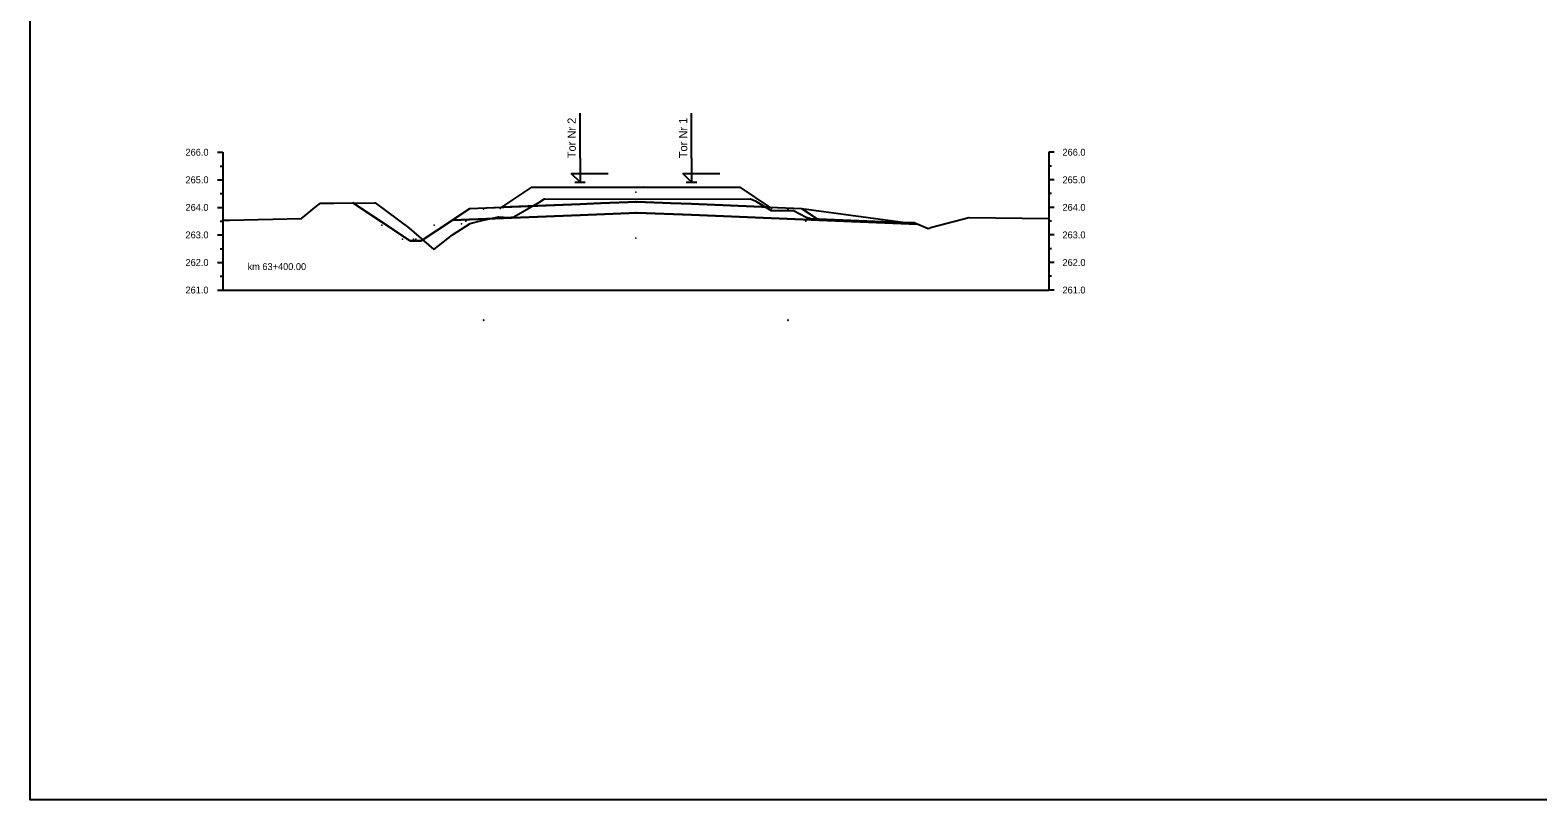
# Model space of a CAD drawing. Extents: x -1 to 65640748, y -22 to 5530284.
# Drawn here: x 2476.3 to 2531.1, y 966.4 to 994.4 of the extents above; entities that cross this region are included whole.
import ezdxf

# ---------------------------------------------------------------- set-up
doc = ezdxf.new("R2010")
doc.units = 0
for name, color, linetype in [('IR_cross_section', 7, 'Continuous'), ('IR_cross_section_tytul', 7, 'Continuous'), ('IR_default', 7, 'Continuous'), ('TOR_PRZEK_P-komponent', 7, 'Continuous'), ('TOR_PRZEK_P-obwiednia robo ziemnych', 7, 'Continuous'), ('TOR_PRZEK_P-odwodnienie', 7, 'Continuous'), ('TOR_PRZEK_P-teren istniejacy', 7, 'Continuous'), ('TOR_PRZEK_P-tluczen+miedzytorze', 7, 'Continuous'), ('TOR_PRZEK_P-tory projektowane', 7, 'Continuous'), ('TOR_PRZEK_P-uklad odniesienia', 7, 'Continuous'), ('TOR_PRZEK_P-warstwa ochronna I', 7, 'Continuous'), ('TOR_PRZEK_P-warstwa ochronna II', 7, 'Continuous')]:
    doc.layers.add(name, color=color, linetype=linetype)

msp = doc.modelspace()

# ---------------------------------------------------------------- linework, layer by layer
for points in [[(2489.55, 987.108), (2488.051, 988.107)], [(2504.352, 987.901), (2504.991, 987.476), (2508.566, 987.333)], [(2490.535, 986.718), (2490.135, 986.718), (2489.55, 987.108)]]:
    msp.add_lwpolyline(points)
at = {"layer": 'IR_cross_section'}
msp.add_lwpolyline([(2476.328, 994.938), (2676.328, 994.938), (2676.328, 966.438), (2476.328, 966.438)], close=True, dxfattribs=at)
at = {"layer": 'IR_default'}
for points in [[(2488.051, 988.107), (2488.857, 987.57), (2489.55, 987.108), (2489.816, 986.93), (2490.135, 986.718), (2490.535, 986.718), (2491.664, 987.471), (2492.303, 987.897), (2493.462, 987.943), (2494.553, 988.67), (2498.052, 988.67), (2498.14, 988.67), (2498.603, 988.67), (2500.126, 988.67), (2502.103, 988.67), (2503.186, 987.948), (2504.352, 987.901), (2504.991, 987.476), (2508.566, 987.333)], [(2486.877, 988.093), (2486.877, 988.094), (2486.877, 988.093), (2486.877, 988.093), (2486.877, 988.093), (2486.878, 988.093), (2486.877, 988.093), (2486.878, 988.094)], [(2488.863, 988.102), (2488.863, 988.103), (2488.863, 988.102), (2488.863, 988.102), (2488.863, 988.102), (2488.864, 988.102), (2488.863, 988.102), (2488.864, 988.103)], [(2495.015, 988.249), (2495.015, 988.25), (2495.015, 988.249), (2495.015, 988.249), (2495.015, 988.249), (2495.016, 988.249), (2495.015, 988.249), (2495.016, 988.25)], [(2502.499, 988.249), (2502.498, 988.25), (2502.499, 988.249), (2502.498, 988.249), (2502.499, 988.249), (2502.499, 988.249), (2502.499, 988.249), (2502.499, 988.25)], [(2486.188, 987.537), (2486.188, 987.537), (2486.188, 987.537), (2486.188, 987.536), (2486.188, 987.537), (2486.189, 987.536), (2486.188, 987.537), (2486.189, 987.537)], [(2492.303, 987.897), (2491.664, 987.471), (2490.535, 986.718)], [(2492.303, 987.897), (2492.302, 987.897), (2492.303, 987.897), (2492.302, 987.896), (2492.303, 987.897), (2492.303, 987.896), (2492.303, 987.897), (2492.303, 987.897)], [(2493.345, 987.598), (2493.345, 987.599), (2493.345, 987.598), (2493.345, 987.598), (2493.345, 987.598), (2493.346, 987.598), (2493.345, 987.598), (2493.346, 987.599)], [(2493.894, 987.59), (2493.893, 987.59), (2493.894, 987.59), (2493.893, 987.589), (2493.894, 987.59), (2493.894, 987.589), (2493.894, 987.59), (2493.894, 987.59)], [(2503.25, 987.83), (2503.249, 987.831), (2503.25, 987.83), (2503.249, 987.83), (2503.25, 987.83), (2503.25, 987.83), (2503.25, 987.83), (2503.25, 987.831)], [(2504.062, 987.824), (2504.062, 987.825), (2504.062, 987.824), (2504.062, 987.824), (2504.062, 987.824), (2504.063, 987.824), (2504.062, 987.824), (2504.063, 987.825)], [(2504.353, 987.901), (2504.352, 987.902), (2504.353, 987.901), (2504.352, 987.901), (2504.353, 987.901), (2504.353, 987.901), (2504.353, 987.901), (2504.353, 987.902)], [(2504.67, 987.536), (2504.67, 987.536), (2504.67, 987.536), (2504.67, 987.535), (2504.67, 987.536), (2504.671, 987.535), (2504.67, 987.536), (2504.671, 987.536)], [(2510.429, 987.565), (2510.428, 987.565), (2510.429, 987.565), (2510.428, 987.564), (2510.429, 987.565), (2510.429, 987.564), (2510.429, 987.565), (2510.429, 987.565)], [(2492.31, 987.351), (2492.31, 987.352), (2492.31, 987.351), (2492.31, 987.351), (2492.31, 987.351), (2492.311, 987.351), (2492.31, 987.351), (2492.311, 987.352)], [(2508.439, 987.386), (2508.439, 987.387), (2508.439, 987.386), (2508.439, 987.386), (2508.439, 987.386), (2508.44, 987.386), (2508.439, 987.386), (2508.44, 987.387)], [(2508.947, 987.171), (2508.946, 987.171), (2508.947, 987.171), (2508.946, 987.17), (2508.947, 987.171), (2508.947, 987.17), (2508.947, 987.171), (2508.947, 987.171)], [(2490.988, 986.413), (2490.987, 986.414), (2490.988, 986.413), (2490.987, 986.413), (2490.988, 986.413), (2490.988, 986.413), (2490.988, 986.413), (2490.988, 986.414)]]:
    msp.add_lwpolyline(points, dxfattribs=at)
at = {"layer": 'TOR_PRZEK_P-komponent'}
msp.add_lwpolyline([(2494.553, 988.67), (2498.052, 988.67), (2498.603, 988.67), (2502.103, 988.67), (2503.186, 987.948), (2500.352, 988.061), (2499.602, 988.091), (2498.383, 988.14), (2497.053, 988.087), (2496.303, 988.057), (2493.462, 987.943), (2493.462, 987.943)], close=True, dxfattribs=at)
for points in [[(2498.054, 988.67), (2498.053, 988.67), (2498.054, 988.67), (2498.053, 988.669), (2498.054, 988.67), (2498.054, 988.669), (2498.054, 988.67), (2498.054, 988.67)], [(2498.602, 988.67), (2498.601, 988.67), (2498.602, 988.67), (2498.601, 988.669), (2498.602, 988.67), (2498.602, 988.669), (2498.602, 988.67), (2498.602, 988.67)], [(2498.327, 988.487), (2498.326, 988.488), (2498.327, 988.487), (2498.326, 988.487), (2498.327, 988.487), (2498.327, 988.487), (2498.327, 988.487), (2498.327, 988.488)], [(2498.329, 988.487), (2498.328, 988.488), (2498.329, 988.487), (2498.328, 988.487), (2498.329, 988.487), (2498.329, 988.487), (2498.329, 988.487), (2498.329, 988.488)]]:
    msp.add_lwpolyline(points, dxfattribs=at)
at = {"layer": 'TOR_PRZEK_P-obwiednia robo ziemnych'}
for points in [[(2487.892, 988.093), (2487.892, 988.094), (2487.892, 988.093), (2487.892, 988.093), (2487.892, 988.093), (2487.893, 988.093), (2487.892, 988.093), (2487.893, 988.094)], [(2487.892, 988.093), (2487.892, 988.094), (2487.892, 988.093), (2487.892, 988.093), (2487.892, 988.093), (2487.893, 988.093), (2487.892, 988.093), (2487.893, 988.094)], [(2488.051, 988.107), (2488.051, 988.107), (2488.051, 988.107), (2488.051, 988.106), (2488.051, 988.107), (2488.052, 988.106), (2488.051, 988.107), (2488.052, 988.107)], [(2488.051, 988.107), (2488.051, 988.107), (2488.051, 988.107), (2488.051, 988.106), (2488.051, 988.107), (2488.052, 988.106), (2488.051, 988.107), (2488.052, 988.107)], [(2489.1, 987.288), (2489.1, 987.288), (2489.1, 987.288), (2489.1, 987.287), (2489.1, 987.288), (2489.101, 987.287), (2489.1, 987.288), (2489.101, 987.288)], [(2489.1, 987.288), (2489.1, 987.288), (2489.1, 987.288), (2489.1, 987.287), (2489.1, 987.288), (2489.101, 987.287), (2489.1, 987.288), (2489.101, 987.288)], [(2491, 987.288), (2490.999, 987.288), (2491, 987.288), (2490.999, 987.287), (2491, 987.288), (2491, 987.287), (2491, 987.288), (2491, 987.288)], [(2491, 987.288), (2490.999, 987.288), (2491, 987.288), (2490.999, 987.287), (2491, 987.288), (2491, 987.287), (2491, 987.288), (2491, 987.288)], [(2492, 987.338), (2491.999, 987.338), (2492, 987.338), (2491.999, 987.337), (2492, 987.338), (2492, 987.337), (2492, 987.338), (2492, 987.338)], [(2492, 987.338), (2491.999, 987.338), (2492, 987.338), (2491.999, 987.337), (2492, 987.338), (2492, 987.337), (2492, 987.338), (2492, 987.338)], [(2492.149, 987.437), (2492.149, 987.438), (2492.149, 987.437), (2492.149, 987.437), (2492.149, 987.437), (2492.15, 987.437), (2492.149, 987.437), (2492.15, 987.438)], [(2492.149, 987.437), (2492.149, 987.438), (2492.149, 987.437), (2492.149, 987.437), (2492.149, 987.437), (2492.15, 987.437), (2492.149, 987.437), (2492.15, 987.438)], [(2489.85, 986.788), (2489.849, 986.788), (2489.85, 986.788), (2489.849, 986.787), (2489.85, 986.788), (2489.85, 986.787), (2489.85, 986.788), (2489.85, 986.788)], [(2489.85, 986.788), (2489.849, 986.788), (2489.85, 986.788), (2489.849, 986.787), (2489.85, 986.788), (2489.85, 986.787), (2489.85, 986.788), (2489.85, 986.788)], [(2490.135, 986.718), (2490.134, 986.718), (2490.135, 986.718), (2490.134, 986.717), (2490.135, 986.718), (2490.135, 986.717), (2490.135, 986.718), (2490.135, 986.718)], [(2490.135, 986.718), (2490.134, 986.718), (2490.135, 986.718), (2490.134, 986.717), (2490.135, 986.718), (2490.135, 986.717), (2490.135, 986.718), (2490.135, 986.718)], [(2490.25, 986.788), (2490.249, 986.788), (2490.25, 986.788), (2490.249, 986.787), (2490.25, 986.788), (2490.25, 986.787), (2490.25, 986.788), (2490.25, 986.788)], [(2490.25, 986.788), (2490.249, 986.788), (2490.25, 986.788), (2490.249, 986.787), (2490.25, 986.788), (2490.25, 986.787), (2490.25, 986.788), (2490.25, 986.788)], [(2490.535, 986.718), (2490.534, 986.718), (2490.535, 986.718), (2490.534, 986.717), (2490.535, 986.718), (2490.535, 986.717), (2490.535, 986.718), (2490.535, 986.718)], [(2490.535, 986.718), (2490.534, 986.718), (2490.535, 986.718), (2490.534, 986.717), (2490.535, 986.718), (2490.535, 986.717), (2490.535, 986.718), (2490.535, 986.718)]]:
    msp.add_lwpolyline(points, dxfattribs=at)
at = {"layer": 'TOR_PRZEK_P-odwodnienie'}
msp.add_lwpolyline([(2490.334, 986.788), (2490.334, 986.788), (2490.334, 986.788), (2490.334, 986.787), (2490.334, 986.788), (2490.335, 986.787), (2490.334, 986.788), (2490.335, 986.788)], dxfattribs=at)
at = {"layer": 'TOR_PRZEK_P-teren istniejacy'}
msp.add_lwpolyline([(2483.328, 987.473), (2483.57, 987.476), (2486.188, 987.537), (2486.732, 987.984), (2486.877, 988.093), (2487.354, 988.088), (2488.863, 988.102), (2490.084, 987.192), (2490.988, 986.413), (2491.674, 986.947), (2492.31, 987.351), (2492.688, 987.453), (2493.345, 987.598), (2493.709, 987.565), (2493.894, 987.59), (2494.84, 988.135), (2495.015, 988.249), (2500.961, 988.241), (2502.499, 988.249), (2502.667, 988.169), (2503.25, 987.83), (2503.931, 987.83), (2504.062, 987.824), (2504.514, 987.586), (2504.67, 987.536), (2508.188, 987.39), (2508.439, 987.386), (2508.947, 987.171), (2509.079, 987.221), (2510.429, 987.565), (2513.328, 987.528)], dxfattribs=at)
at = {"layer": 'TOR_PRZEK_P-tluczen+miedzytorze'}
for points in [[(2494.553, 988.67), (2494.552, 988.67), (2494.553, 988.67), (2494.552, 988.669), (2494.553, 988.67), (2494.553, 988.669), (2494.553, 988.67), (2494.553, 988.67)], [(2494.553, 988.67), (2494.552, 988.67), (2494.553, 988.67), (2494.552, 988.669), (2494.553, 988.67), (2494.553, 988.669), (2494.553, 988.67), (2494.553, 988.67)], [(2496.303, 988.67), (2496.302, 988.67), (2496.303, 988.67), (2496.302, 988.669), (2496.303, 988.67), (2496.303, 988.669), (2496.303, 988.67), (2496.303, 988.67)], [(2497.059, 988.67), (2497.058, 988.67), (2497.059, 988.67), (2497.058, 988.669), (2497.059, 988.67), (2497.059, 988.669), (2497.059, 988.67), (2497.059, 988.67)], [(2498.053, 988.67), (2498.052, 988.67), (2498.053, 988.67), (2498.052, 988.669), (2498.053, 988.67), (2498.053, 988.669), (2498.053, 988.67), (2498.053, 988.67)], [(2498.053, 988.67), (2498.052, 988.67), (2498.053, 988.67), (2498.052, 988.669), (2498.053, 988.67), (2498.053, 988.669), (2498.053, 988.67), (2498.053, 988.67)], [(2498.603, 988.67), (2498.602, 988.67), (2498.603, 988.67), (2498.602, 988.669), (2498.603, 988.67), (2498.603, 988.669), (2498.603, 988.67), (2498.603, 988.67)], [(2498.603, 988.67), (2498.602, 988.67), (2498.603, 988.67), (2498.602, 988.669), (2498.603, 988.67), (2498.603, 988.669), (2498.603, 988.67), (2498.603, 988.67)], [(2499.597, 988.67), (2499.596, 988.67), (2499.597, 988.67), (2499.596, 988.669), (2499.597, 988.67), (2499.597, 988.669), (2499.597, 988.67), (2499.597, 988.67)], [(2500.353, 988.67), (2500.352, 988.67), (2500.353, 988.67), (2500.352, 988.669), (2500.353, 988.67), (2500.353, 988.669), (2500.353, 988.67), (2500.353, 988.67)], [(2502.103, 988.67), (2502.102, 988.67), (2502.103, 988.67), (2502.102, 988.669), (2502.103, 988.67), (2502.103, 988.669), (2502.103, 988.67), (2502.103, 988.67)], [(2502.103, 988.67), (2502.102, 988.67), (2502.103, 988.67), (2502.102, 988.669), (2502.103, 988.67), (2502.103, 988.669), (2502.103, 988.67), (2502.103, 988.67)], [(2497.059, 988.083), (2497.058, 988.083), (2497.059, 988.083), (2497.058, 988.082), (2497.059, 988.083), (2497.059, 988.082), (2497.059, 988.083), (2497.059, 988.083)], [(2498.327, 988.487), (2498.326, 988.488), (2498.327, 988.487), (2498.326, 988.487), (2498.327, 988.487), (2498.327, 988.487), (2498.327, 988.487), (2498.327, 988.488)], [(2498.327, 988.487), (2498.326, 988.488), (2498.327, 988.487), (2498.326, 988.487), (2498.327, 988.487), (2498.327, 988.487), (2498.327, 988.487), (2498.327, 988.488)], [(2498.327, 988.146), (2498.326, 988.147), (2498.327, 988.146), (2498.326, 988.146), (2498.327, 988.146), (2498.327, 988.146), (2498.327, 988.146), (2498.327, 988.147)], [(2498.327, 988.146), (2498.326, 988.147), (2498.327, 988.146), (2498.326, 988.146), (2498.327, 988.146), (2498.327, 988.146), (2498.327, 988.146), (2498.327, 988.147)], [(2498.329, 988.487), (2498.328, 988.488), (2498.329, 988.487), (2498.328, 988.487), (2498.329, 988.487), (2498.329, 988.487), (2498.329, 988.487), (2498.329, 988.488)], [(2498.329, 988.487), (2498.328, 988.488), (2498.329, 988.487), (2498.328, 988.487), (2498.329, 988.487), (2498.329, 988.487), (2498.329, 988.487), (2498.329, 988.488)], [(2498.329, 988.146), (2498.328, 988.147), (2498.329, 988.146), (2498.328, 988.146), (2498.329, 988.146), (2498.329, 988.146), (2498.329, 988.146), (2498.329, 988.147)], [(2498.329, 988.146), (2498.328, 988.147), (2498.329, 988.146), (2498.328, 988.146), (2498.329, 988.146), (2498.329, 988.146), (2498.329, 988.146), (2498.329, 988.147)], [(2499.597, 988.083), (2499.596, 988.083), (2499.597, 988.083), (2499.596, 988.082), (2499.597, 988.083), (2499.597, 988.082), (2499.597, 988.083), (2499.597, 988.083)], [(2493.398, 987.9), (2493.397, 987.9), (2493.398, 987.9), (2493.397, 987.899), (2493.398, 987.9), (2493.398, 987.899), (2493.398, 987.9), (2493.398, 987.9)], [(2493.398, 987.9), (2493.397, 987.9), (2493.398, 987.9), (2493.397, 987.899), (2493.398, 987.9), (2493.398, 987.899), (2493.398, 987.9), (2493.398, 987.9)], [(2493.462, 987.943), (2493.461, 987.943), (2493.462, 987.943), (2493.461, 987.942), (2493.462, 987.943), (2493.462, 987.942), (2493.462, 987.943), (2493.462, 987.943)], [(2503.258, 987.9), (2503.257, 987.9), (2503.258, 987.9), (2503.257, 987.899), (2503.258, 987.9), (2503.258, 987.899), (2503.258, 987.9), (2503.258, 987.9)], [(2503.258, 987.9), (2503.257, 987.9), (2503.258, 987.9), (2503.257, 987.899), (2503.258, 987.9), (2503.258, 987.899), (2503.258, 987.9), (2503.258, 987.9)], [(2492.798, 983.85), (2492.797, 983.85), (2492.798, 983.85), (2492.797, 983.849), (2492.798, 983.85), (2492.798, 983.849), (2492.798, 983.85), (2492.798, 983.85)], [(2492.803, 983.85), (2492.802, 983.85), (2492.803, 983.85), (2492.802, 983.849), (2492.803, 983.85), (2492.803, 983.849), (2492.803, 983.85), (2492.803, 983.85)], [(2503.853, 983.85), (2503.852, 983.85), (2503.853, 983.85), (2503.852, 983.849), (2503.853, 983.85), (2503.853, 983.849), (2503.853, 983.85), (2503.853, 983.85)], [(2503.858, 983.85), (2503.857, 983.85), (2503.858, 983.85), (2503.857, 983.849), (2503.858, 983.85), (2503.858, 983.849), (2503.858, 983.85), (2503.858, 983.85)]]:
    msp.add_lwpolyline(points, dxfattribs=at)
at = {"layer": 'TOR_PRZEK_P-tory projektowane'}
for p, q in [((2496.303, 989.727), (2496.303, 991.36)), ((2496.303, 989.727), (2496.303, 991.36)), ((2500.352, 989.727), (2500.352, 991.36)), ((2500.353, 989.727), (2500.353, 991.36)), ((2496.303, 989.727), (2496.303, 988.85)), ((2496.303, 989.727), (2496.303, 988.85)), ((2500.352, 989.727), (2500.352, 988.85)), ((2500.353, 989.727), (2500.353, 988.85)), ((2496.303, 988.85), (2495.983, 989.169)), ((2495.983, 989.169), (2497.328, 989.169)), ((2496.303, 988.85), (2495.984, 989.169)), ((2495.984, 989.169), (2497.328, 989.169)), ((2500.352, 988.85), (2500.033, 989.169)), ((2500.033, 989.169), (2501.377, 989.169)), ((2500.353, 988.85), (2500.034, 989.169)), ((2500.034, 989.169), (2501.378, 989.169)), ((2496.111, 988.85), (2496.494, 988.85)), ((2496.111, 988.85), (2496.494, 988.85)), ((2500.161, 988.85), (2500.544, 988.85)), ((2500.161, 988.85), (2500.544, 988.85))]:
    msp.add_line(p, q, dxfattribs=at)
at = {"layer": 'TOR_PRZEK_P-uklad odniesienia'}
for p, q in [((2483.128, 989.938), (2483.328, 989.938)), ((2483.328, 989.938), (2483.328, 984.938)), ((2513.328, 989.938), (2513.328, 984.938)), ((2513.528, 989.938), (2513.328, 989.938)), ((2483.228, 989.438), (2483.328, 989.438)), ((2513.428, 989.438), (2513.328, 989.438)), ((2483.128, 988.938), (2483.328, 988.938)), ((2513.528, 988.938), (2513.328, 988.938)), ((2483.228, 988.438), (2483.328, 988.438)), ((2513.428, 988.438), (2513.328, 988.438)), ((2483.128, 987.938), (2483.328, 987.938)), ((2513.528, 987.938), (2513.328, 987.938)), ((2483.128, 986.938), (2483.328, 986.938)), ((2483.228, 987.438), (2483.328, 987.438)), ((2513.428, 987.438), (2513.328, 987.438)), ((2513.528, 986.938), (2513.328, 986.938)), ((2483.228, 986.438), (2483.328, 986.438)), ((2513.428, 986.438), (2513.328, 986.438)), ((2483.128, 985.938), (2483.328, 985.938)), ((2513.528, 985.938), (2513.328, 985.938)), ((2483.228, 985.438), (2483.328, 985.438)), ((2513.428, 985.438), (2513.328, 985.438)), ((2483.128, 984.938), (2483.328, 984.938)), ((2483.328, 984.938), (2513.328, 984.938)), ((2513.528, 984.938), (2513.328, 984.938))]:
    msp.add_line(p, q, dxfattribs=at)
at = {"layer": 'TOR_PRZEK_P-warstwa ochronna I'}
for points in [[(2498.326, 988.146), (2498.326, 988.147), (2498.326, 988.146), (2498.326, 988.146), (2498.326, 988.146), (2498.327, 988.146), (2498.326, 988.146), (2498.327, 988.147)], [(2498.329, 988.146), (2498.328, 988.147), (2498.329, 988.146), (2498.328, 988.146), (2498.329, 988.146), (2498.329, 988.146), (2498.329, 988.146), (2498.329, 988.147)], [(2491.664, 987.471), (2496.303, 987.657), (2498.383, 987.74), (2500.353, 987.661), (2504.991, 987.475)], [(2492.798, 987.87), (2492.797, 987.87), (2492.798, 987.87), (2492.797, 987.869), (2492.798, 987.87), (2492.798, 987.869), (2492.798, 987.87), (2492.798, 987.87)], [(2492.798, 987.87), (2492.797, 987.87), (2492.798, 987.87), (2492.797, 987.869), (2492.798, 987.87), (2492.798, 987.869), (2492.798, 987.87), (2492.798, 987.87)], [(2492.798, 987.87), (2492.797, 987.87), (2492.798, 987.87), (2492.797, 987.869), (2492.798, 987.87), (2492.798, 987.869), (2492.798, 987.87), (2492.798, 987.87)], [(2498.329, 987.746), (2498.328, 987.747), (2498.329, 987.746), (2498.328, 987.746), (2498.329, 987.746), (2498.329, 987.746), (2498.329, 987.746), (2498.329, 987.747)], [(2498.329, 987.746), (2498.328, 987.747), (2498.329, 987.746), (2498.328, 987.746), (2498.329, 987.746), (2498.329, 987.746), (2498.329, 987.746), (2498.329, 987.747)], [(2498.329, 987.746), (2498.328, 987.747), (2498.329, 987.746), (2498.328, 987.746), (2498.329, 987.746), (2498.329, 987.746), (2498.329, 987.746), (2498.329, 987.747)], [(2498.329, 987.746), (2498.328, 987.747), (2498.329, 987.746), (2498.328, 987.746), (2498.329, 987.746), (2498.329, 987.746), (2498.329, 987.746), (2498.329, 987.747)], [(2503.858, 987.87), (2503.857, 987.87), (2503.858, 987.87), (2503.857, 987.869), (2503.858, 987.87), (2503.858, 987.869), (2503.858, 987.87), (2503.858, 987.87)], [(2503.858, 987.87), (2503.857, 987.87), (2503.858, 987.87), (2503.857, 987.869), (2503.858, 987.87), (2503.858, 987.869), (2503.858, 987.87), (2503.858, 987.87)], [(2503.858, 987.87), (2503.857, 987.87), (2503.858, 987.87), (2503.857, 987.869), (2503.858, 987.87), (2503.858, 987.869), (2503.858, 987.87), (2503.858, 987.87)], [(2492.15, 987.437), (2492.149, 987.438), (2492.15, 987.437), (2492.149, 987.437), (2492.15, 987.437), (2492.15, 987.437), (2492.15, 987.437), (2492.15, 987.438)], [(2492.15, 987.437), (2492.149, 987.438), (2492.15, 987.437), (2492.149, 987.437), (2492.15, 987.437), (2492.15, 987.437), (2492.15, 987.437), (2492.15, 987.438)], [(2504.506, 987.437), (2504.506, 987.438), (2504.506, 987.437), (2504.506, 987.437), (2504.506, 987.437), (2504.507, 987.437), (2504.506, 987.437), (2504.507, 987.438)], [(2504.506, 987.437), (2504.506, 987.438), (2504.506, 987.437), (2504.506, 987.437), (2504.506, 987.437), (2504.507, 987.437), (2504.506, 987.437), (2504.507, 987.438)], [(2498.328, 986.825), (2498.327, 986.825), (2498.328, 986.825), (2498.327, 986.824), (2498.328, 986.825), (2498.328, 986.824), (2498.328, 986.825), (2498.328, 986.825)]]:
    msp.add_lwpolyline(points, dxfattribs=at)
at = {"layer": 'TOR_PRZEK_P-warstwa ochronna II'}
msp.add_lwpolyline([(2488.051, 988.107), (2490.135, 986.718), (2490.535, 986.718), (2492.303, 987.897), (2496.303, 988.057), (2497.053, 988.087), (2498.383, 988.14), (2499.603, 988.091), (2500.353, 988.061), (2503.186, 987.948), (2504.353, 987.901), (2508.566, 987.332)], dxfattribs=at)
msp.add_lwpolyline([(2493.462, 987.943), (2493.462, 987.943), (2496.303, 988.057), (2497.053, 988.087), (2498.383, 988.14), (2499.602, 988.091), (2500.352, 988.061), (2503.186, 987.948), (2504.352, 987.901), (2504.991, 987.476), (2500.352, 987.661), (2498.383, 987.74), (2496.303, 987.657), (2491.664, 987.471), (2492.303, 987.897)], close=True, dxfattribs=at)

# ---------------------------------------------------------------- texts
at = {"layer": 'IR_cross_section_tytul'}
msp.add_text('km 63+400.00', height=0.25, dxfattribs=at).set_placement((2484.225, 985.663))
at = {"layer": 'TOR_PRZEK_P-tory projektowane'}
for s, p in [('Tor Nr 2', (2496.148, 989.721)), ('Tor Nr 2', (2496.148, 989.721)), ('Tor Nr 1', (2500.198, 989.721)), ('Tor Nr 1', (2500.198, 989.721))]:
    msp.add_text(s, height=0.3, rotation=90, dxfattribs=at).set_placement(p)
at = {"layer": 'TOR_PRZEK_P-uklad odniesienia'}
for s, p in [('266.0', (2481.971, 989.813)), ('266.0', (2513.828, 989.813)), ('265.0', (2481.971, 988.813)), ('265.0', (2513.828, 988.813)), ('264.0', (2481.971, 987.813)), ('264.0', (2513.828, 987.813)), ('263.0', (2481.971, 986.813)), ('263.0', (2513.828, 986.813)), ('262.0', (2481.971, 985.813)), ('262.0', (2513.828, 985.813)), ('261.0', (2481.971, 984.813)), ('261.0', (2513.828, 984.813))]:
    msp.add_text(s, height=0.25, dxfattribs=at).set_placement(p)

doc.saveas('drawing.dxf')
